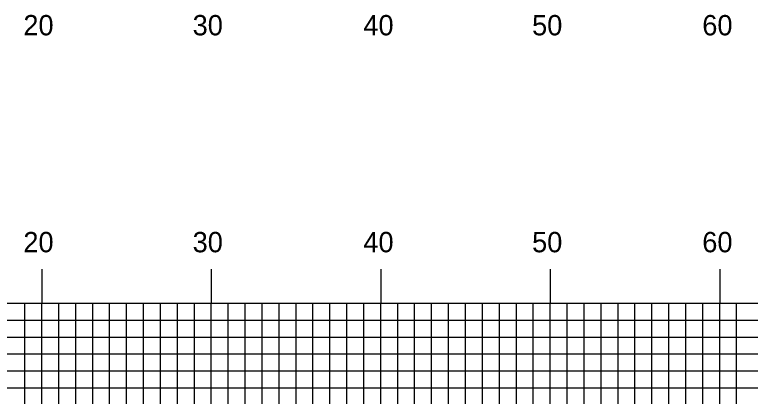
# Model space of a CAD drawing. Extents: x 1804290 to 1804634, y 442591 to 442811.
# Drawn here: x 1804474.57 to 1804517.97, y 442673.17 to 442695.68 of the extents above; entities that cross this region are included whole.
import ezdxf

# ---------------------------------------------------------------- set-up
doc = ezdxf.new("R2010")
doc.units = 0
for name, color, linetype in [('H_V ANNOTATION', 7, 'Continuous'), ('MAJOR', 7, 'Continuous'), ('MINOR', 7, 'Continuous')]:
    doc.layers.add(name, color=color, linetype=linetype)

msp = doc.modelspace()

# ---------------------------------------------------------------- linework, layer by layer
at = {"layer": 'MAJOR'}
for p, q in [((1804476.167, 442680.669), (1804476.167, 442678.665)), ((1804486.167, 442680.669), (1804486.167, 442678.665)), ((1804496.167, 442680.669), (1804496.167, 442678.665)), ((1804506.167, 442680.669), (1804506.167, 442678.665)), ((1804516.167, 442680.669), (1804516.167, 442678.665)), ((1804316.167, 442678.665), (1804596.167, 442678.665)), ((1804316.167, 442678.665), (1804596.167, 442678.665)), ((1804476.167, 442653.665), (1804476.167, 442678.665)), ((1804486.167, 442653.665), (1804486.167, 442678.665)), ((1804496.167, 442653.665), (1804496.167, 442678.665)), ((1804506.167, 442653.665), (1804506.167, 442678.665)), ((1804516.167, 442653.665), (1804516.167, 442678.665)), ((1804316.167, 442673.665), (1804596.167, 442673.665))]:
    msp.add_line(p, q, dxfattribs=at)
at = {"layer": 'MINOR'}
for p, q in [((1804475.167, 442653.665), (1804475.167, 442678.665)), ((1804477.167, 442653.665), (1804477.167, 442678.665)), ((1804478.167, 442653.665), (1804478.167, 442678.665)), ((1804479.167, 442653.665), (1804479.167, 442678.665)), ((1804480.167, 442653.665), (1804480.167, 442678.665)), ((1804481.167, 442653.665), (1804481.167, 442678.665)), ((1804482.167, 442653.665), (1804482.167, 442678.665)), ((1804483.167, 442653.665), (1804483.167, 442678.665)), ((1804484.167, 442653.665), (1804484.167, 442678.665)), ((1804485.167, 442653.665), (1804485.167, 442678.665)), ((1804487.167, 442653.665), (1804487.167, 442678.665)), ((1804488.167, 442653.665), (1804488.167, 442678.665)), ((1804489.167, 442653.665), (1804489.167, 442678.665)), ((1804490.167, 442653.665), (1804490.167, 442678.665)), ((1804491.167, 442653.665), (1804491.167, 442678.665)), ((1804492.167, 442653.665), (1804492.167, 442678.665)), ((1804493.167, 442653.665), (1804493.167, 442678.665)), ((1804494.167, 442653.665), (1804494.167, 442678.665)), ((1804495.167, 442653.665), (1804495.167, 442678.665)), ((1804497.167, 442653.665), (1804497.167, 442678.665)), ((1804498.167, 442653.665), (1804498.167, 442678.665)), ((1804499.167, 442653.665), (1804499.167, 442678.665)), ((1804500.167, 442653.665), (1804500.167, 442678.665)), ((1804501.167, 442653.665), (1804501.167, 442678.665)), ((1804502.167, 442653.665), (1804502.167, 442678.665)), ((1804503.167, 442653.665), (1804503.167, 442678.665)), ((1804504.167, 442653.665), (1804504.167, 442678.665)), ((1804505.167, 442653.665), (1804505.167, 442678.665)), ((1804507.167, 442653.665), (1804507.167, 442678.665)), ((1804508.167, 442653.665), (1804508.167, 442678.665)), ((1804509.167, 442653.665), (1804509.167, 442678.665)), ((1804510.167, 442653.665), (1804510.167, 442678.665)), ((1804511.167, 442653.665), (1804511.167, 442678.665)), ((1804512.167, 442653.665), (1804512.167, 442678.665)), ((1804513.167, 442653.665), (1804513.167, 442678.665)), ((1804514.167, 442653.665), (1804514.167, 442678.665)), ((1804515.167, 442653.665), (1804515.167, 442678.665)), ((1804517.167, 442653.665), (1804517.167, 442678.665)), ((1804316.167, 442677.665), (1804596.167, 442677.665)), ((1804316.167, 442676.665), (1804596.167, 442676.665)), ((1804316.167, 442675.665), (1804596.167, 442675.665)), ((1804316.167, 442674.665), (1804596.167, 442674.665))]:
    msp.add_line(p, q, dxfattribs=at)

# ---------------------------------------------------------------- texts
at = {"layer": 'H_V ANNOTATION'}
for s, p in [('20', (1804475.075, 442694.465)), ('30', (1804485.064, 442694.465)), ('40', (1804495.139, 442694.465)), ('50', (1804505.096, 442694.465)), ('60', (1804515.139, 442694.465)), ('20', (1804475.075, 442681.665)), ('30', (1804485.064, 442681.665)), ('40', (1804495.139, 442681.665)), ('50', (1804505.096, 442681.665)), ('60', (1804515.139, 442681.665))]:
    msp.add_text(s, height=1.2, dxfattribs=at).set_placement(p)

doc.saveas('drawing.dxf')
